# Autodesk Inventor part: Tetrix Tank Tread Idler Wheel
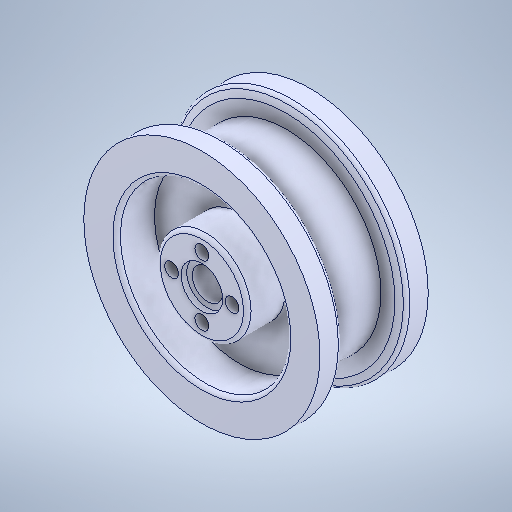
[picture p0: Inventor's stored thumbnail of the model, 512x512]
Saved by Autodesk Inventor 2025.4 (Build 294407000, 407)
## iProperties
Created: 2021-10
Part Number: Tetrix Tank Tread Idler Wheel
Material: Genérico
Document SubType Name: Modeling
Designer: usuario
Density: 1 g/cm^3
Appearance: Valor por defecto
Author: usuario
Sending System: SolidWorks 2016
Last Author: LENOVO
Last Saved: 2021-10-21
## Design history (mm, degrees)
fillet "Fillet1"
node "Plane1"
node "Sólido1"
